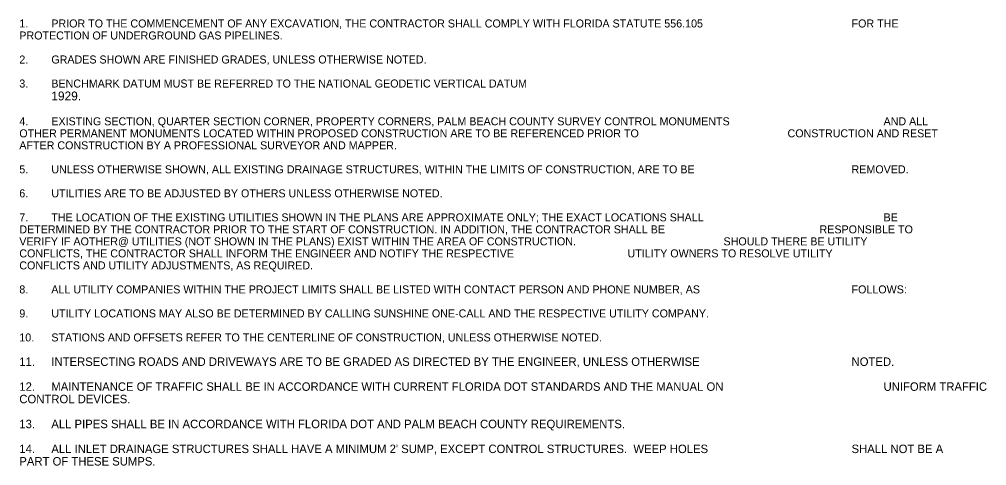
# Model space of a CAD drawing. Extents: x 783907 to 784590, y 832310 to 832609.
# Drawn here: x 784002.1 to 784086.7, y 832393.5 to 832432.5 of the extents above; entities that cross this region are included whole.
import ezdxf

# ---------------------------------------------------------------- set-up
doc = ezdxf.new("R2010")
doc.units = 0
doc.layers.add('Miscellaneous0', color=7, linetype='Continuous')

msp = doc.modelspace()

# ---------------------------------------------------------------- texts
at = {"layer": 'Miscellaneous0'}
for s, height, p in [('1.', 0.7, (784002.096, 832431.818)), ('PRIOR TO THE COMMENCEMENT OF ANY EXCAVATION, THE CONTRACTOR SHALL COMPLY WITH FLORIDA STATUTE 556.105 ', 0.7, (784004.896, 832431.818)), ('FOR THE ', 0.7, (784074.896, 832431.818)), ('PROTECTION OF UNDERGROUND GAS PIPELINES.', 0.7, (784002.096, 832430.768)), ('2.', 0.7, (784002.096, 832428.668)), ('GRADES SHOWN ARE FINISHED GRADES, UNLESS OTHERWISE NOTED.', 0.7, (784004.896, 832428.668)), ('3.', 0.7, (784002.096, 832426.568)), ('BENCHMARK DATUM MUST BE REFERRED TO THE NATIONAL GEODETIC VERTICAL DATUM', 0.7, (784004.896, 832426.568)), ('1929.', 0.7778, (784004.896, 832425.44)), ('4.', 0.7, (784002.096, 832423.263)), ('EXISTING SECTION, QUARTER SECTION CORNER, PROPERTY CORNERS, PALM BEACH COUNTY SURVEY CONTROL MONUMENTS ', 0.7, (784004.896, 832423.263)), ('AND ALL ', 0.7, (784077.696, 832423.263)), ('OTHER PERMANENT MONUMENTS LOCATED WITHIN PROPOSED CONSTRUCTION ARE TO BE REFERENCED PRIOR TO ', 0.7, (784002.096, 832422.213)), ('CONSTRUCTION AND RESET ', 0.7, (784069.296, 832422.213)), ('AFTER CONSTRUCTION BY A PROFESSIONAL SURVEYOR AND MAPPER.', 0.7, (784002.096, 832421.163)), ('5.', 0.7, (784002.096, 832419.063)), ('UNLESS OTHERWISE SHOWN, ALL EXISTING DRAINAGE STRUCTURES, WITHIN THE LIMITS OF CONSTRUCTION, ARE TO BE ', 0.7, (784004.896, 832419.063)), ('REMOVED.', 0.7, (784074.896, 832419.063)), ('6.', 0.7, (784002.096, 832416.963)), ('UTILITIES ARE TO BE ADJUSTED BY OTHERS UNLESS OTHERWISE NOTED.', 0.7, (784004.896, 832416.963)), ('7.', 0.7, (784002.096, 832414.863)), ('THE LOCATION OF THE EXISTING UTILITIES SHOWN IN THE PLANS ARE APPROXIMATE ONLY; THE EXACT LOCATIONS SHALL ', 0.7, (784004.896, 832414.863)), ('BE ', 0.7, (784077.696, 832414.863)), ('DETERMINED BY THE CONTRACTOR PRIOR TO THE START OF CONSTRUCTION. IN ADDITION, THE CONTRACTOR SHALL BE ', 0.7, (784002.096, 832413.813)), ('RESPONSIBLE TO ', 0.7, (784072.096, 832413.813)), ('VERIFY IF AOTHER@ UTILITIES (NOT SHOWN IN THE PLANS) EXIST WITHIN THE AREA OF CONSTRUCTION. ', 0.7, (784002.096, 832412.763)), ('SHOULD THERE BE UTILITY ', 0.7, (784063.696, 832412.763)), ('CONFLICTS, THE CONTRACTOR SHALL INFORM THE ENGINEER AND NOTIFY THE RESPECTIVE ', 0.7, (784002.096, 832411.713)), ('UTILITY OWNERS TO RESOLVE UTILITY ', 0.7, (784055.296, 832411.713)), ('CONFLICTS AND UTILITY ADJUSTMENTS, AS REQUIRED.', 0.7, (784002.096, 832410.663)), ('8.', 0.7, (784002.096, 832408.563)), ('ALL UTILITY COMPANIES WITHIN THE PROJECT LIMITS SHALL BE LISTED WITH CONTACT PERSON AND PHONE NUMBER, AS ', 0.7, (784004.896, 832408.563)), ('FOLLOWS:', 0.7, (784074.896, 832408.563)), ('9.', 0.7, (784002.096, 832406.463)), ('UTILITY LOCATIONS MAY ALSO BE DETERMINED BY CALLING SUNSHINE ONE-CALL AND THE RESPECTIVE UTILITY COMPANY.', 0.7, (784004.896, 832406.463)), ('10.', 0.7, (784002.096, 832404.363)), ('STATIONS AND OFFSETS REFER TO THE CENTERLINE OF CONSTRUCTION, UNLESS OTHERWISE NOTED.', 0.7, (784004.896, 832404.363)), ('11.', 0.7389, (784002.096, 832402.224)), ('INTERSECTING ROADS AND DRIVEWAYS ARE TO BE GRADED AS DIRECTED BY THE ENGINEER, UNLESS OTHERWISE ', 0.73889, (784004.896, 832402.224)), ('NOTED.', 0.7389, (784074.896, 832402.224)), ('12.', 0.7389, (784002.096, 832400.046)), ('MAINTENANCE OF TRAFFIC SHALL BE IN ACCORDANCE WITH CURRENT FLORIDA DOT STANDARDS AND THE MANUAL ON ', 0.73889, (784004.896, 832400.046)), ('UNIFORM TRAFFIC ', 0.73889, (784077.696, 832400.046)), ('CONTROL DEVICES.', 0.73889, (784002.096, 832398.957)), ('13.', 0.7389, (784002.096, 832396.779)), ('ALL PIPES SHALL BE IN ACCORDANCE WITH FLORIDA DOT AND PALM BEACH COUNTY REQUIREMENTS.', 0.73889, (784004.896, 832396.779)), ('14.', 0.7389, (784002.096, 832394.602)), ("ALL INLET DRAINAGE STRUCTURES SHALL HAVE A MINIMUM 2' SUMP, EXCEPT CONTROL STRUCTURES.  WEEP HOLES ", 0.73889, (784004.896, 832394.602)), ('SHALL NOT BE A ', 0.73889, (784074.896, 832394.602)), ('PART OF THESE SUMPS.', 0.73889, (784002.096, 832393.513))]:
    msp.add_text(s, height=height, dxfattribs=at).set_placement(p)

doc.saveas('drawing.dxf')
